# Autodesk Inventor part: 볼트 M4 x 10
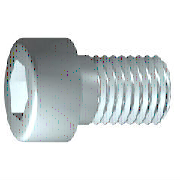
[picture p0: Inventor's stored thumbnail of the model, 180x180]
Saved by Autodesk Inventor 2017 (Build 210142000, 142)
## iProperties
IsCustomPart: 0
Created: 2012-02
Part Number: 볼트 M4 x 10
Material: 스테인리스강
Description: 6각 소켓 머리 캡 나사
Document SubType Name: Modeling
Standard: ISO 4762
Designer: mduedu
Standard Revision: Fourth edition 2004-03-01
Standards Organization: ISO
Language: ko-KR
Size Designation: M4 x 10
Categories: <MemberInstance><Categories><Category DisplayName="조임쇠" InternalName="e4da775c-781d-43d5-af7c-5136215cf5a6" Mnemonic="FSTN"><Category DisplayName="볼트" InternalN
Density: 8.08 g/cm^3
Appearance: 반광택
Author: mduedu
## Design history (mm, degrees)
sketch "스케치1"
  geometry: L1 (-1, 0)-(10, 0); L2 (10, 0)-(10, 2); L3 (10, 2)-(1.75, 2); L4 (1.75, 2)-(1.32, 2); L5 (1.32, 2)-(0, 2); L6 (0, 2)-(0, 3.5); L7 (0, 3.5)-(-4, 3.5); L8 (-4, 3.5)-(-4, 1.732); L9 (-4, 1.732)-(-2, 1.732); L10 (-2, 1.732)-(-1, 0); L11 (-6.8, 0)-(12.8, 0) reference; L12 (0, -0.7)-(0, 4.2) reference; L13 (1.75, 2)-(0, 2)
  constraints: 22 end point, 6 parallel, 2 collinear, 2 perpendicular, 1 horizontal, 1 point on line
  dimensions: "d1" = 8.25 distance from line of L3.end L2 (= GEL); "d2" = 0.42952 distance of L4.end L3.end (computed from GAL); "d3" = 4 distance between parallel lines of L8 L6 (= KOH); "d4" = 2 distance of L8.end L9.end (= INTI); "d5" = 60 deg angle of L10 L1; "d6" = 4 diameter of L3 L1 (= GD); "d7" = 4 diameter of L5 L1 (= BDM); "d8" = 3.4641 diameter of L9 L1 (= 1.1547 x SW); "d9" = 7 diameter of L7 L1 (= KOD); "d26" = 10 distance between parallel lines of L12 L2 (= NLG)
revolve "본체" sketch "스케치1" stored, may be unused: angle "d10" = 90 deg
sketch "스케치2"
  geometry: L1 (0, -4.9)-(0, 4.9) reference; L2 (-4.9, 0)-(4.9, 0) reference; L3 (1.732, 0)-(0.866, -1.5); L4 (0.866, -1.5)-(-0.866, -1.5); L5 (-0.866, -1.5)-(-1.732, 0); L6 (-1.732, 0)-(-0.866, 1.5); L7 (-0.866, 1.5)-(0.866, 1.5); L8 (0.866, 1.5)-(1.732, 0); 2 further points
  constraints: 12 end point, 1 coincident, 1 horizontal alignment, 1 point on line, 12 other
extrude "슬롯" join sketch "스케치2" stored distance "d11" = 10; taper "d12" = 0 deg
workplane "Work Plane1"
fillet "Fillet2" dims "d30" = 0.1 (= R)
body "Solid1"
fillet "모깎기1" dims "d17" = 0.4 (= RR)
feature "스레드" dims "d13" = 8.25 (= GEL), "d14" = 0
chamfer "모따기1" distance "d15" = 0.42941 (= -0.5 x SPD + 0.5 x GD); stored, may be unused: second distance "d16" = 0.42941 (= GUL), angle "d27" = 45 deg
other parameters: "GD" = 4 [user parameter; used in 2 equation terms], "NLG" = 10 [user parameter; used in 1 equation term], "GEL" = 8.25 [user parameter; used in 2 equation terms], "KOD" = 7 [user parameter; used in 1 equation term], "KOH" = 4 [user parameter; used in 1 equation term], "INTI" = 2 [user parameter; used in 1 equation term], "GAL" = 0.42941 (= 0.61345 x PTC) [user parameter; used in 1 equation term], "GUL" = 0.42941 (= 0.61345 x PTC) [user parameter; used in 1 equation term], "BDM" = 4 (= NND) [user parameter; used in 1 equation term], "SW" = 3 [user parameter; used in 2 equation terms], "RR" = 0.4 [user parameter; used in 1 equation term], "SPD" = 3.14117 (= NND - 1.2269 x PTC) [user parameter; used in 1 equation term], "d19" = 0, "d28" = 0, "d29" = 0, "R" = 0.1 [user parameter; used in 1 equation term], "TOA" = 30 deg [user parameter], "GD1" = 3.14117 (= THREADDIA - 1.2269 x PTC) [user parameter], "THREADDIA" = 4 [user parameter; used in 1 equation term], "FAWI" = 45 deg [user parameter], "TPU" = 14.28571 (computed from PTC) [user parameter], "PTC" = 0.7 [user parameter; used in 5 equation terms], "NND" = 4 [user parameter; used in 2 equation terms], "E0" = 3.465 (= 1.155 x SW) [user parameter]
